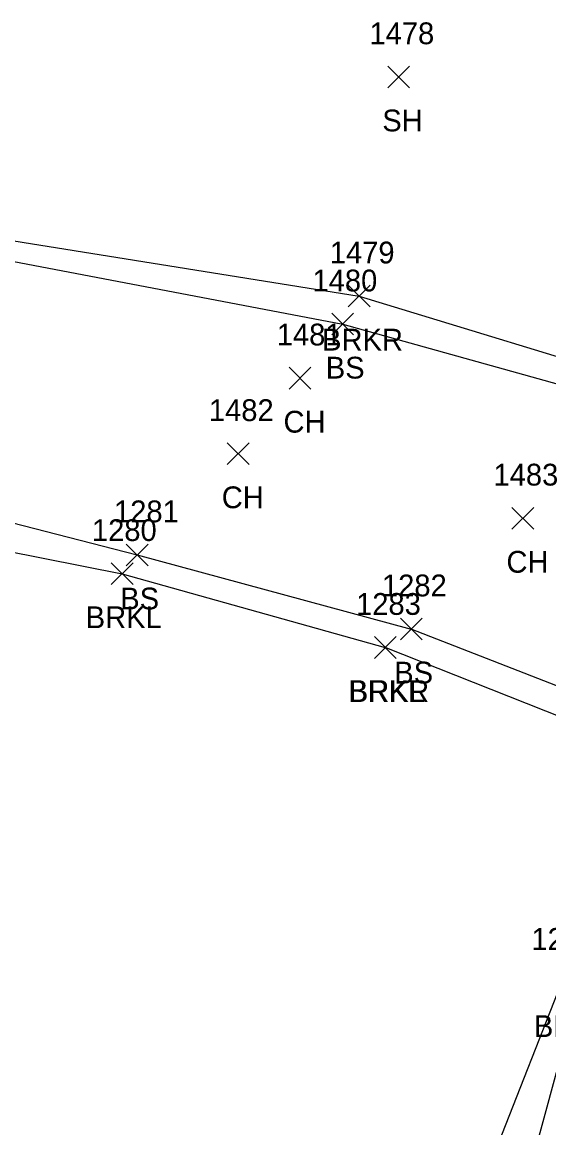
# Model space of a CAD drawing. Extents: x 1654425 to 1656893, y 667839 to 678429.
# Drawn here: x 1654499.7 to 1654548, y 668323.6 to 668425.1 of the extents above; entities that cross this region are included whole.
import ezdxf

# ---------------------------------------------------------------- set-up
doc = ezdxf.new("R2010")
doc.units = 0
for name, color, linetype in [('L_A', 7, 'Continuous'), ('L_I', 7, 'Continuous'), ('L_TIC', 7, 'Continuous'), ('LABL', 7, 'Continuous'), ('LAWE', 7, 'Continuous'), ('LELB', 7, 'Continuous')]:
    doc.layers.add(name, color=color, linetype=linetype)

msp = doc.modelspace()

# ---------------------------------------------------------------- linework, layer by layer
at = {"layer": 'L_TIC'}
for points in [[(1654533.25, 668419.03), (1654535.25, 668421.03)], [(1654535.25, 668419.03), (1654533.25, 668421.03)], [(1654529.62, 668398.91), (1654531.62, 668400.91)], [(1654531.62, 668398.91), (1654529.62, 668400.91)], [(1654528.11, 668396.34), (1654530.11, 668398.34)], [(1654530.11, 668396.34), (1654528.11, 668398.34)], [(1654524.18, 668391.38), (1654526.18, 668393.38)], [(1654526.18, 668391.38), (1654524.18, 668393.38)], [(1654518.51, 668384.44), (1654520.51, 668386.44)], [(1654520.51, 668384.44), (1654518.51, 668386.44)], [(1654544.65, 668378.52), (1654546.65, 668380.52)], [(1654546.65, 668378.52), (1654544.65, 668380.52)], [(1654509.24, 668375.15), (1654511.24, 668377.15)], [(1654511.24, 668375.15), (1654509.24, 668377.15)], [(1654507.86, 668373.43), (1654509.86, 668375.43)], [(1654509.86, 668373.43), (1654507.86, 668375.43)], [(1654534.4, 668368.35), (1654536.4, 668370.35)], [(1654536.4, 668368.35), (1654534.4, 668370.35)], [(1654534.4, 668368.35), (1654536.4, 668370.35)], [(1654536.4, 668368.35), (1654534.4, 668370.35)], [(1654532.02, 668366.65), (1654534.02, 668368.65)], [(1654534.02, 668366.65), (1654532.02, 668368.65)], [(1654532.02, 668366.65), (1654534.02, 668368.65)], [(1654534.02, 668366.65), (1654532.02, 668368.65)]]:
    msp.add_lwpolyline(points, dxfattribs=at)
at = {"layer": 'LABL'}
msp.add_lwpolyline([(1654560.74, 668356.68), (1654555.56, 668348.04), (1654549.18, 668336.9), (1654537.5, 668307.15)], dxfattribs=at)
at = {"layer": 'LAWE'}
for points in [[(1654445.7, 668421.51), (1654494.11, 668405.75), (1654530.62, 668399.91), (1654558.13, 668391.51)], [(1654434.88, 668392.54), (1654476.27, 668380.87), (1654508.86, 668374.43), (1654533.02, 668367.65)], [(1654560.74, 668356.68), (1654533.02, 668367.65)]]:
    msp.add_lwpolyline(points, dxfattribs=at)
at = {"layer": 'LELB'}
for points in [[(1654445.04, 668417.26), (1654493.58, 668404.1), (1654529.11, 668397.34), (1654556.9, 668389.59)], [(1654436.42, 668396.22), (1654477.74, 668384.51), (1654510.24, 668376.15), (1654535.4, 668369.35)], [(1654719.24, 668210.51), (1654718.56, 668239.52), (1654712.25, 668254.01), (1654698.51, 668263.45), (1654673.53, 668283.65), (1654654.27, 668317.98), (1654633.02, 668335.94), (1654624.64, 668338.82), (1654619.07, 668342.23), (1654579.05, 668354.59), (1654565.49, 668358.45), (1654562.65, 668358.71), (1654535.4, 668369.35)], [(1654562.65, 668358.71), (1654556.85, 668347.4), (1654550.86, 668336.48), (1654541.59, 668302.56), (1654534.79, 668276.13), (1654518.99, 668243.67), (1654496.56, 668205), (1654493.42, 668170.69)]]:
    msp.add_lwpolyline(points, dxfattribs=at)

# ---------------------------------------------------------------- texts
at = {"layer": 'L_A'}
for s, p in [('SH', (1654532.74, 668415.03)), ('BRKR', (1654527.21, 668394.91)), ('BS', (1654527.55, 668392.34)), ('CH', (1654523.67, 668387.38)), ('CH', (1654518, 668380.44)), ('CH', (1654544.14, 668374.52)), ('BS', (1654508.68, 668371.15)), ('BRKL', (1654505.51, 668369.43)), ('BS', (1654533.84, 668364.35)), ('BS', (1654533.84, 668364.35)), ('BRKR', (1654529.61, 668362.65)), ('BRKL', (1654529.67, 668362.65)), ('BRR', (1654546.66, 668331.9))]:
    msp.add_text(s, height=2, dxfattribs=at).set_placement(p)
at = {"layer": 'L_I'}
for s, p in [('1478', (1654531.56, 668423.03)), ('1479', (1654527.92, 668402.91)), ('1480', (1654526.33, 668400.34)), ('1481', (1654523.05, 668395.38)), ('1482', (1654516.82, 668388.44)), ('1483', (1654542.95, 668382.52)), ('1281', (1654508.11, 668379.15)), ('1280', (1654506.08, 668377.43)), ('1282', (1654532.71, 668372.35)), ('1282', (1654532.71, 668372.35)), ('1283', (1654530.33, 668370.65)), ('1283', (1654530.33, 668370.65)), ('1256', (1654546.43, 668339.9))]:
    msp.add_text(s, height=2, dxfattribs=at).set_placement(p)

doc.saveas('drawing.dxf')
